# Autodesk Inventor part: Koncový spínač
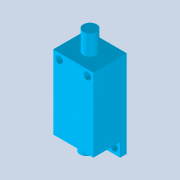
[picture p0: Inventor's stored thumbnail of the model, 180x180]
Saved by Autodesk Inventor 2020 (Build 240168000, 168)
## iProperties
Created: 2025-03
Part Number: Koncový spínač
Material: Polypropylen
Document SubType Name: Modeling
Designer: doma
Density: 0.899 g/cm^3
Appearance: Nebeská modrá – střední
Author: doma
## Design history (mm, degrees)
sketch "Náčrt1"
  geometry: L1 (-15, -32.5)-(15, -32.5); L2 (15, -32.5)-(15, 32.5); L3 (15, 32.5)-(-15, 32.5); L4 (-15, 32.5)-(-15, -32.5); L5 (-15, -32.5)-(15, 32.5); L6 (15, -32.5)-(-15, 32.5); 1 further point
  constraints: 12 end point, 2 midpoint, 2 parallel, 1 horizontal, 1 perpendicular
  dimensions: "d0" = 30 distance of L3.end L2.end; "d1" = 65 distance of L2.end L1.end
extrude "Vysunutí1" new body sketch "Náčrt1" distance "d2" = 25; taper "d3" = 0 deg
sketch "Náčrt2"
  geometry: L1 (15, -32.5)-(15, 32.5) reference; L2 (-15, 32.5)-(-15, -32.5) reference; L3 (15, -32.5)-(-15, -32.5); L4 (-15, -32.5)-(-15, -22.5); L5 (-15, -22.5)-(15, -22.5); L6 (15, -22.5)-(15, -32.5); 3 further points
  constraints: 8 end point, 2 parallel, 1 horizontal, 1 perpendicular, 1 point on line
  dimensions: "d6" = 10 distance between parallel lines of L3 L5
extrude "Vysunutí2" cut sketch "Náčrt2" distance "d4" = 20; taper "d5" = 0 deg
sketch "Náčrt3"
  geometry: C1 r 5 at (15, -12.5); 1 further point
  constraints: 1 centre point
  dimensions: "d7" = 10 diameter of C1
extrude "Vysunutí3" join sketch "Náčrt3" distance "d8" = 15; taper "d9" = 0 deg
sketch "Náčrt4"
  geometry: L1 (-10.5, -28)-(10.5, -28); L2 (10.5, -28)-(10.5, 28); L3 (10.5, 28)-(-10.5, 28); L4 (-10.5, 28)-(-10.5, -28); L5 (-10.5, -28)-(10.5, 28); L6 (10.5, -28)-(-10.5, 28); 5 further points
  constraints: 12 end point, 4 coincident, 2 midpoint, 2 parallel, 1 horizontal, 1 perpendicular
  dimensions: "d10" = 21 distance of L2.end L3.end; "d11" = 56 distance of L1.end L2.end
hole "Díra1" sketch "Náčrt4" at (-10.5, 28), (10.5, 28), (10.5, -28), (-10.5, -28) diameter "d12" = 5.5; stored, may be unused: countersink angle "d16" = 90 deg, drill point angle "d18" = 118 deg; dims "d13" = 24, "d14" = 4, "d15" = 2, "d17" = 8
sketch "Náčrt5"
  geometry: L1 (0, 0)-(30, 0) reference; L2 (0, -20)-(0, 0) reference; L3 (30, -20)-(0, -20) reference; L4 (30, 0)-(30, -20) reference; L5 (30, 0)-(0, 0) reference; L6 (15, 0)-(15, -20); L7 (0, -20)-(30, -20) reference; C1 r 5 at (15, -10); 1 further point
  constraints: 3 midpoint, 2 end point, 1 centre point
  dimensions: "d19" = 10 diameter of C1
extrude "Vysunutí4" join sketch "Náčrt5" distance "d20" = 8; taper "d21" = 0 deg
node "Těleso1"
